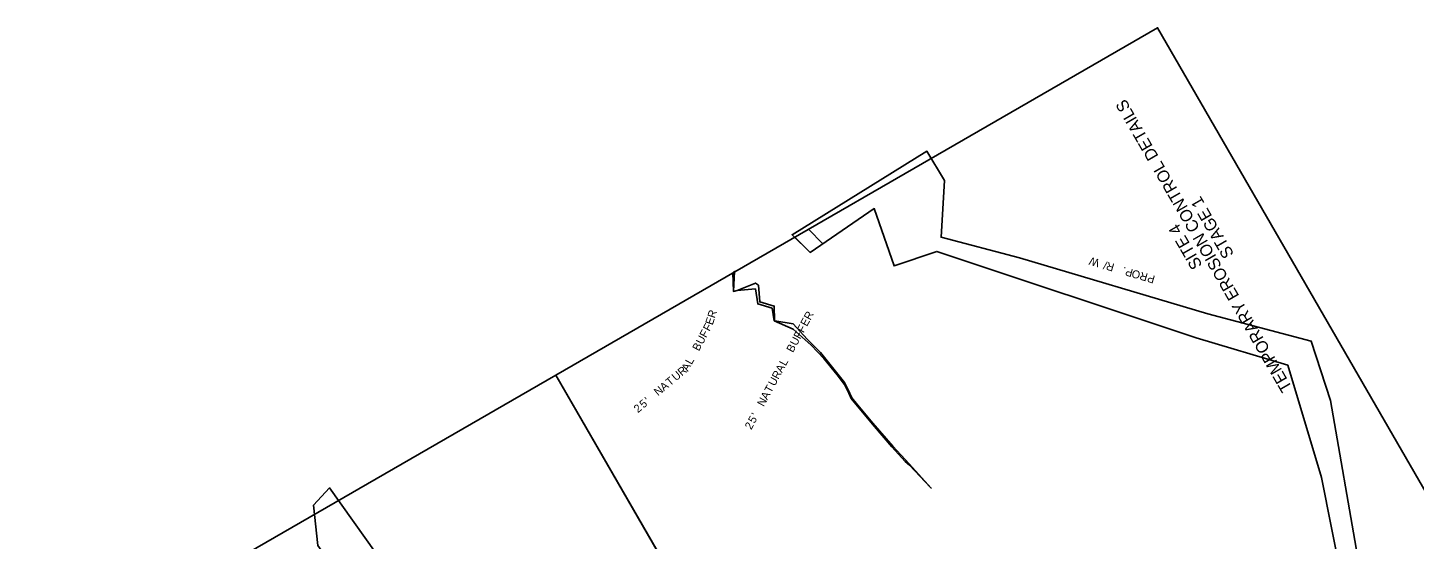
# Model space of a CAD drawing. Extents: x 956270 to 957915, y 1920520 to 1922423.
# Drawn here: x 956270 to 957310, y 1922039 to 1922423 of the extents above; entities that cross this region are included whole.
import ezdxf

# ---------------------------------------------------------------- set-up
doc = ezdxf.new("R2010")
doc.units = 0
for name, color, linetype in [('1', 7, 'Continuous'), ('60', 7, 'Continuous'), ('NO PLOT', 7, 'Continuous'), ('R_Draft', 7, 'Continuous'), ('R_Drainage', 7, 'Continuous'), ('R_Horz Alg', 7, 'Continuous')]:
    doc.layers.add(name, color=color, linetype=linetype)

msp = doc.modelspace()

# ---------------------------------------------------------------- linework, layer by layer
at = {"layer": '1'}
msp.add_line((956816.7, 1921902), (956666.2, 1922162.6), dxfattribs=at)
at = {"layer": 'NO PLOT'}
for points in [[(957915.2, 1921041.6), (957117.5, 1922423.2), (956666.2, 1922162.6), (956816.7, 1921902), (956875.1, 1921935.7), (957087.6, 1921567.7), (957029.2, 1921533.9), (957172.3, 1921286.1), (957225.7, 1921317), (957397.1, 1921020.2), (957343.6, 1920989.3), (957463.8, 1920781)], [(957915.2, 1921041.6), (957117.5, 1922423.2), (956666.2, 1922162.6), (956816.7, 1921902), (956875.1, 1921935.7), (957087.6, 1921567.7), (957029.2, 1921533.9), (957172.3, 1921286.1), (957225.7, 1921317), (957397.1, 1921020.2), (957343.6, 1920989.3), (957463.8, 1920781)], [(957915.2, 1921041.6), (957117.5, 1922423.2), (956666.2, 1922162.6), (956816.7, 1921902), (956875.1, 1921935.7), (957087.6, 1921567.7), (957029.2, 1921533.9), (957172.3, 1921286.1), (957225.7, 1921317), (957397.1, 1921020.2), (957343.6, 1920989.3), (957463.8, 1920781)], [(957915.2, 1921041.6), (957117.5, 1922423.2), (956666.2, 1922162.6), (956816.7, 1921902), (956875.1, 1921935.7), (957087.6, 1921567.7), (957029.2, 1921533.9), (957172.3, 1921286.1), (957225.7, 1921317), (957397.1, 1921020.2), (957343.6, 1920989.3), (957463.8, 1920781)], [(956931.4, 1922095), (956947.3, 1922078.3), (956947.8, 1922077.9), (956947.8, 1922077.9), (956931.3, 1922096.1), (956918.9, 1922109.4), (956904, 1922126.7), (956891.4, 1922141.7), (956888.2, 1922145.5), (956885.4, 1922151.7), (956882.6, 1922157), (956864.8, 1922179.5), (956854.6, 1922189.7), (956844.3, 1922201), (956830.4, 1922203.4), (956830.1, 1922203.5), (956830.1, 1922203.7), (956830, 1922214.4), (956819.1, 1922217.5), (956818.2, 1922230.1), (956815.9, 1922231.7), (956802.3, 1922226.1), (956802.1, 1922226.1), (956799.4, 1922225.4), (956800.2, 1922240.5), (956798.9, 1922239.4), (956799.4, 1922225.4), (956802.1, 1922226.1), (956815.9, 1922227.3), (956817.7, 1922216), (956828.4, 1922212.8), (956830, 1922203.4), (956844.2, 1922197.2), (956857.7, 1922185.2), (956867.2, 1922175.1), (956877.2, 1922162.8), (956883.1, 1922154.9), (956884.7, 1922151.5), (956885.9, 1922149), (956887.8, 1922145.1), (956891.3, 1922140.9), (956903.8, 1922125.9), (956918.3, 1922108.8), (956928.3, 1922097.8)], [(957012.5, 1920520.4), (956420.5, 1921545.9), (956463.3, 1921570.6), (956365.4, 1921740.1), (956378, 1921747.4), (956270.3, 1921934.1), (956666.2, 1922162.6), (956816.7, 1921902), (956750, 1921863.5), (956962.5, 1921495.4), (957029.2, 1921533.9), (957172.3, 1921286.1), (957120.9, 1921256.4), (957292.2, 1920959.7), (957343.6, 1920989.3), (957463.8, 1920781)], [(957012.5, 1920520.4), (956420.5, 1921545.9), (956463.3, 1921570.6), (956365.4, 1921740.1), (956378, 1921747.4), (956270.3, 1921934.1), (956666.2, 1922162.6), (956816.7, 1921902), (956750, 1921863.5), (956962.5, 1921495.4), (957029.2, 1921533.9), (957172.3, 1921286.1), (957120.9, 1921256.4), (957292.2, 1920959.7), (957343.6, 1920989.3), (957463.8, 1920781)], [(957012.5, 1920520.4), (956420.5, 1921545.9), (956463.3, 1921570.6), (956365.4, 1921740.1), (956378, 1921747.4), (956270.3, 1921934.1), (956666.2, 1922162.6), (956816.7, 1921902), (956750, 1921863.5), (956962.5, 1921495.4), (957029.2, 1921533.9), (957172.3, 1921286.1), (957120.9, 1921256.4), (957292.2, 1920959.7), (957343.6, 1920989.3), (957463.8, 1920781)], [(957012.5, 1920520.4), (956420.5, 1921545.9), (956463.3, 1921570.6), (956365.4, 1921740.1), (956378, 1921747.4), (956270.3, 1921934.1), (956666.2, 1922162.6), (956816.7, 1921902), (956750, 1921863.5), (956962.5, 1921495.4), (957029.2, 1921533.9), (957172.3, 1921286.1), (957120.9, 1921256.4), (957292.2, 1920959.7), (957343.6, 1920989.3), (957463.8, 1920781)]]:
    msp.add_lwpolyline(points, close=True, dxfattribs=at)
for points in [[(957267.4, 1922027.1), (957247, 1922143.6), (957232.7, 1922188.1), (957155.2, 1922208.5), (957013.9, 1922250.7), (956955.1, 1922266.1), (956957.7, 1922308.6), (956944.5, 1922330.6), (956843.4, 1922267.9), (956857, 1922254.7), (956905, 1922287.5), (956919.9, 1922244.6), (956952, 1922255.4), (957146.3, 1922190.5), (957215, 1922170), (957240.3, 1922085.9), (957255.1, 1922011.6)], [(956978.4, 1921301), (956892, 1921416.3), (956761.2, 1921624.8), (956685.7, 1921817.7), (956598.6, 1922001.4), (956569.2, 1922006.8), (956549.4, 1922003.6), (956496.6, 1922078), (956484.6, 1922065.1), (956487.7, 1922034.9), (956520.1, 1921988.8), (956538.4, 1921986.1), (956552.8, 1921975.4), (956577.9, 1921905.7), (956667.6, 1921797.4), (956675.5, 1921786), (956734.3, 1921643), (956883.9, 1921386.2), (956963.4, 1921282.8)]]:
    msp.add_lwpolyline(points, dxfattribs=at)
at = {"layer": 'R_Drainage'}
msp.add_lwpolyline([(956857, 1922254.7), (956845.4, 1922266.1)], dxfattribs=at)
at = {"layer": 'R_Horz Alg'}
msp.add_line((956866.5, 1922261.2), (956855.7, 1922272), dxfattribs=at)

# ---------------------------------------------------------------- texts
at = {"layer": '60'}
for s, p in [('TEMPORARY EROSION CONTROL DETAILS', (957218.7, 1922153.1)), ('STAGE 1', (957175, 1922253.4)), ('SITE 4', (957151.3, 1922245.1))]:
    msp.add_text(s, height=9, rotation=120, dxfattribs=at).set_placement(p)
at = {"layer": 'R_Draft'}
for s, rotation, p in [('W', 163.5297, (957074.5, 1922249.2)), ('/', 163.5297, (957080.1, 1922247.6)), ('R', 163.5297, (957085.5, 1922246)), ('.', 163.5297, (957094.1, 1922243.4)), ('P', 163.5297, (957099.5, 1922241.8)), ('O', 163.5297, (957105.1, 1922240.2)), ('R', 163.5297, (957110.6, 1922238.6)), ('P', 163.5297, (957116, 1922237)), ('E', 71.8782, (956783.8, 1922199.8)), ('R', 71.8782, (956785.4, 1922204.9)), ('E', 61.6353, (956854.5, 1922198.7)), ('R', 61.6353, (956857.1, 1922203.4)), ('F', 61.6353, (956778.9, 1922190.2)), ('F', 61.6353, (956781.5, 1922195)), ('F', 61.6353, (956849.4, 1922189.2)), ('F', 61.6353, (956852, 1922193.9)), ('B', 61.6353, (956773.5, 1922180.2)), ('U', 61.6353, (956776.2, 1922185.1)), ('B', 61.6353, (956844, 1922179.1)), ('U', 61.6353, (956846.7, 1922184.1)), ('L', 61.6353, (956768.1, 1922170.1)), ('L', 61.6353, (956838.6, 1922169.1)), ('T', 39.9648, (956751.8, 1922154.1)), ('U', 39.9648, (956756.3, 1922157.9)), ('R', 39.9648, (956760.7, 1922161.6)), ('A', 61.6353, (956765.3, 1922165)), ('R', 61.6353, (956833.1, 1922159)), ('A', 61.6353, (956835.8, 1922164)), ('N', 39.9648, (956742.9, 1922146.7)), ('A', 39.9648, (956747.3, 1922150.3)), ('T', 61.6353, (956827.6, 1922148.7)), ('U', 61.6353, (956830.4, 1922153.9)), ('5', 39.9648, (956732, 1922137.5)), ("'", 39.9648, (956736.1, 1922141)), ('N', 61.6353, (956822.1, 1922138.6)), ('A', 61.6353, (956824.8, 1922143.6)), ('2', 39.9648, (956727.8, 1922134)), ('5', 61.6353, (956815.3, 1922126)), ("'", 61.6353, (956817.9, 1922130.7)), ('2', 61.6353, (956812.8, 1922121.3))]:
    msp.add_text(s, height=6, rotation=rotation, dxfattribs=at).set_placement(p)

doc.saveas('drawing.dxf')
